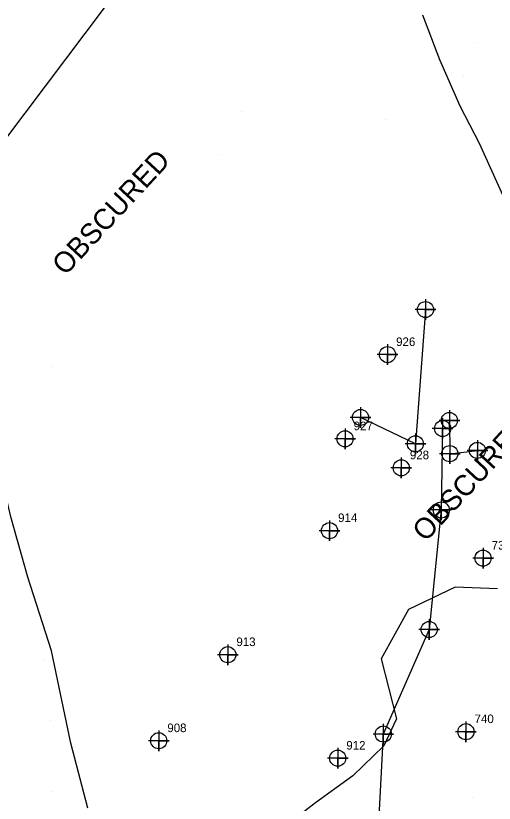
# Model space of a CAD drawing. Extents: x 1497074 to 1501343, y 481943 to 486114.
# Drawn here: x 1498751 to 1498890.1, y 485245.1 to 485474.1 of the extents above; entities that cross this region are included whole.
import ezdxf

# ---------------------------------------------------------------- set-up
doc = ezdxf.new("R2010")
doc.units = 0
for name, color, linetype in [('Exist DTM Breakline', 7, 'Continuous'), ('Exist DTM Breakline Cogo Point CELL', 7, 'Continuous'), ('Exist DTM Regular Point CELL', 7, 'Continuous'), ('Exist DTM Regular Point Cogo Number', 7, 'Continuous'), ('Exist Roads EOP Other', 7, 'Continuous'), ('Exist Roads EOP Other Cogo Point CELL', 7, 'Continuous'), ('PH Exist DTM Boundary', 7, 'Continuous'), ('PH Exist DTM Obscure Area', 7, 'Continuous'), ('PH Exist DTM Obscure Area Text', 7, 'Continuous'), ('PH Exist DTM Point', 7, 'Continuous')]:
    doc.layers.add(name, color=color, linetype=linetype)

msp = doc.modelspace()

# ---------------------------------------------------------------- linework, layer by layer
at = {"layer": 'Exist DTM Breakline'}
for points in [[(1498870.08, 485388.64), (1498867.15, 485349.6), (1498851.2, 485357.28)], [(1498875.06, 485354.05), (1498874.67, 485330.37), (1498871.16, 485295.61), (1498857.83, 485265.22), (1498856.36, 485237.55), (1498849.81, 485218.2), (1498817.78, 485196.25), (1498792.66, 485178.23), (1498788.46, 485157.78), (1498791.08, 485130.91)]]:
    msp.add_lwpolyline(points, dxfattribs=at)
at = {"layer": 'Exist DTM Breakline Cogo Point CELL'}
for points in [[(1498870.08, 485391.64), (1498870.08, 485385.64), (1498870.08, 485388.64), (1498873.08, 485388.64), (1498867.08, 485388.64)], [(1498851.2, 485360.28), (1498851.2, 485354.28), (1498851.2, 485357.28), (1498854.2, 485357.28), (1498848.2, 485357.28)], [(1498875.06, 485357.05), (1498875.06, 485351.05), (1498875.06, 485354.05), (1498878.06, 485354.05), (1498872.06, 485354.05)], [(1498867.15, 485352.6), (1498867.15, 485346.6), (1498867.15, 485349.6), (1498870.15, 485349.6), (1498864.15, 485349.6)], [(1498874.67, 485333.37), (1498874.67, 485327.37), (1498874.67, 485330.37), (1498877.67, 485330.37), (1498871.67, 485330.37)], [(1498871.16, 485298.61), (1498871.16, 485292.61), (1498871.16, 485295.61), (1498874.16, 485295.61), (1498868.16, 485295.61)], [(1498857.83, 485268.22), (1498857.83, 485262.22), (1498857.83, 485265.22), (1498860.83, 485265.22), (1498854.83, 485265.22)]]:
    msp.add_lwpolyline(points, dxfattribs=at)
for centre in [(1498870.08, 485388.64), (1498851.2, 485357.28), (1498875.06, 485354.05), (1498867.15, 485349.6), (1498874.67, 485330.37), (1498871.16, 485295.61), (1498857.83, 485265.22)]:
    msp.add_circle(centre, 2.34, dxfattribs=at)
at = {"layer": 'Exist DTM Regular Point CELL'}
for points in [[(1498859.05, 485378.54), (1498859.05, 485372.54), (1498859.05, 485375.54), (1498862.05, 485375.54), (1498856.05, 485375.54)], [(1498846.71, 485354.06), (1498846.71, 485348.06), (1498846.71, 485351.06), (1498849.71, 485351.06), (1498843.71, 485351.06)], [(1498863.05, 485345.61), (1498863.05, 485339.61), (1498863.05, 485342.61), (1498866.05, 485342.61), (1498860.05, 485342.61)], [(1498842.19, 485327.35), (1498842.19, 485321.35), (1498842.19, 485324.35), (1498845.19, 485324.35), (1498839.19, 485324.35)], [(1498886.81, 485319.36), (1498886.81, 485313.36), (1498886.81, 485316.36), (1498889.81, 485316.36), (1498883.81, 485316.36)], [(1498812.62, 485291.29), (1498812.62, 485285.29), (1498812.62, 485288.29), (1498815.62, 485288.29), (1498809.62, 485288.29)], [(1498881.85, 485268.9), (1498881.85, 485262.9), (1498881.85, 485265.9), (1498884.85, 485265.9), (1498878.85, 485265.9)], [(1498792.54, 485266.27), (1498792.54, 485260.27), (1498792.54, 485263.27), (1498795.54, 485263.27), (1498789.54, 485263.27)], [(1498844.57, 485261.19), (1498844.57, 485255.19), (1498844.57, 485258.19), (1498847.57, 485258.19), (1498841.57, 485258.19)]]:
    msp.add_lwpolyline(points, dxfattribs=at)
for centre in [(1498859.05, 485375.54), (1498846.71, 485351.06), (1498863.05, 485342.61), (1498842.19, 485324.35), (1498886.81, 485316.36), (1498812.62, 485288.29), (1498881.85, 485265.9), (1498792.54, 485263.27), (1498844.57, 485258.19)]:
    msp.add_circle(centre, 2.34, dxfattribs=at)
at = {"layer": 'Exist Roads EOP Other'}
msp.add_lwpolyline([(1498877.03, 485356.4), (1498877.16, 485346.74), (1498885.16, 485347.69)], dxfattribs=at)
at = {"layer": 'Exist Roads EOP Other Cogo Point CELL'}
for points in [[(1498877.03, 485359.4), (1498877.03, 485353.4), (1498877.03, 485356.4), (1498880.03, 485356.4), (1498874.03, 485356.4)], [(1498885.16, 485350.69), (1498885.16, 485344.69), (1498885.16, 485347.69), (1498888.16, 485347.69), (1498882.16, 485347.69)], [(1498877.16, 485349.74), (1498877.16, 485343.74), (1498877.16, 485346.74), (1498880.16, 485346.74), (1498874.16, 485346.74)]]:
    msp.add_lwpolyline(points, dxfattribs=at)
for centre in [(1498877.03, 485356.4), (1498885.16, 485347.69), (1498877.16, 485346.74)]:
    msp.add_circle(centre, 2.34, dxfattribs=at)
at = {"layer": 'PH Exist DTM Boundary'}
msp.add_lwpolyline([(1498924.23, 484841.06), (1498545.19, 485168.9), (1498846.5, 485569.16), (1499227.59, 485244.03)], close=True, dxfattribs=at)
at = {"layer": 'PH Exist DTM Obscure Area'}
for points in [[(1498869.22, 485474.32), (1498874.17, 485461.34), (1498880.06, 485447.88), (1498885.73, 485437.06), (1498896.25, 485413.7)], [(1498771.93, 485243.66), (1498766.97, 485262.52), (1498761.4, 485289.45), (1498754.51, 485310.84), (1498749.54, 485328.34), (1498745.24, 485346.3), (1498744.95, 485364.88), (1498743.94, 485378.56), (1498742.94, 485394.04), (1498742.1, 485409.61), (1498741.15, 485424.3), (1498739.62, 485437.23), (1498735.73, 485454.27)], [(1498891.06, 485307.45), (1498878.74, 485307.88), (1498865.18, 485301.39), (1498857.23, 485287.11), (1498861.65, 485269.68), (1498857.97, 485261.83), (1498849, 485253.03), (1498838.14, 485245.17), (1498828.74, 485237.96)]]:
    msp.add_lwpolyline(points, dxfattribs=at)
at = {"layer": 'PH Exist DTM Point'}
for p, q in [((1498884.21, 485466.33), (1498884.21, 485466.33)), ((1498881.05, 485456.56), (1498881.05, 485456.56)), ((1498816.55, 485446.17), (1498816.55, 485446.17)), ((1498858.47, 485443.98), (1498858.47, 485443.98)), ((1498810.72, 485433.76), (1498810.72, 485433.76)), ((1498761.65, 485372.17), (1498761.65, 485372.17)), ((1498759.35, 485286.63), (1498759.35, 485286.63)), ((1498761.17, 485269.04), (1498761.17, 485269.04)), ((1498761.73, 485248.51), (1498761.73, 485248.51)), ((1498883.76, 485246.65), (1498883.76, 485246.65))]:
    msp.add_line(p, q, dxfattribs=at)

# ---------------------------------------------------------------- texts
at = {"layer": 'Exist DTM Regular Point Cogo Number'}
for s, p in [('926', (1498861.55, 485378.04)), ('927', (1498849.21, 485353.56)), ('928', (1498865.55, 485345.11)), ('914', (1498844.69, 485326.85)), ('738', (1498889.31, 485318.86)), ('913', (1498815.12, 485290.79)), ('740', (1498884.35, 485268.4)), ('908', (1498795.04, 485265.77)), ('912', (1498847.07, 485260.69))]:
    msp.add_text(s, height=2.5, dxfattribs=at).set_placement(p)
at = {"layer": 'PH Exist DTM Obscure Area Text'}
for p in [(1498765.38, 485398.27), (1498870.11, 485320.86)]:
    msp.add_text('OBSCURED', height=6, rotation=47.2398, dxfattribs=at).set_placement(p)

doc.saveas('drawing.dxf')
